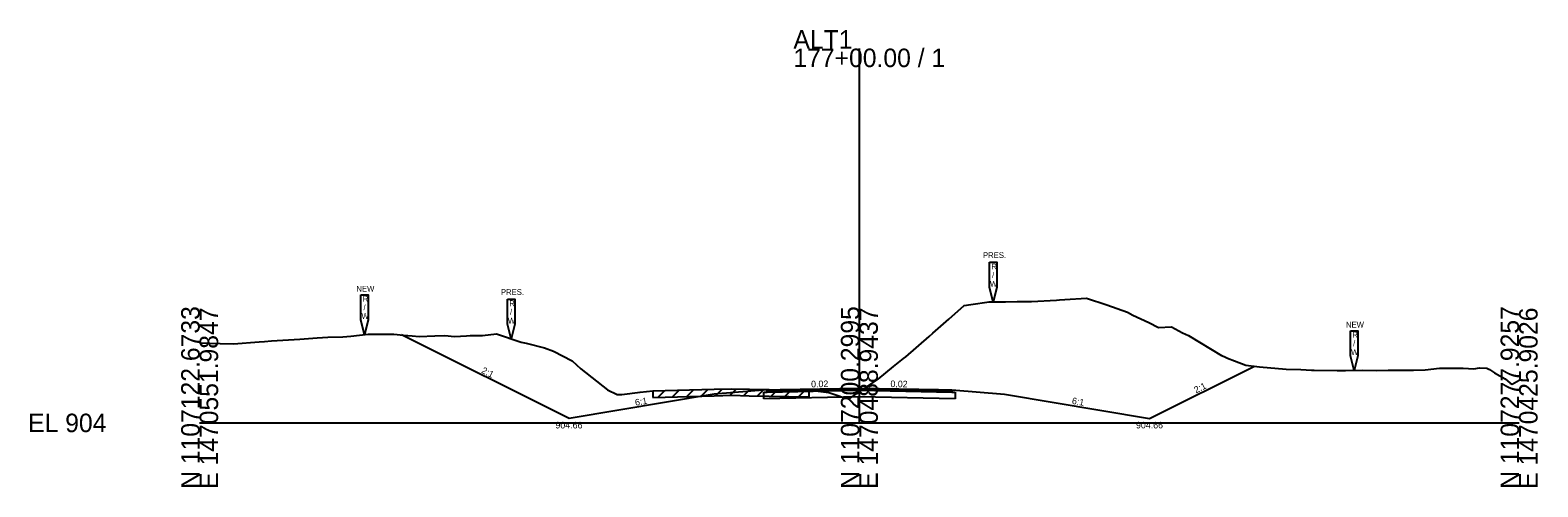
# Model space of a CAD drawing. Extents: x -26 to 2203, y -10 to 19568.
# Drawn here: x 974.3 to 1202.8, y 18990.3 to 19059.5 of the extents above; entities that cross this region are included whole.
import ezdxf

# ---------------------------------------------------------------- set-up
doc = ezdxf.new("R2010")
doc.units = 0
for name, color, linetype in [('RD_GPK_XS_Cell', 7, 'Continuous'), ('RD_XS_Base', 7, 'Continuous'), ('RD_XS_ExGround', 7, 'Continuous'), ('RD_XS_ExPaveRet', 7, 'Continuous'), ('RD_XS_ExRW', 7, 'Continuous'), ('RD_XS_Greenside', 7, 'Continuous'), ('RD_XS_NewRW', 7, 'Continuous'), ('RD_XS_Pave', 7, 'Continuous'), ('RD_XS_TieSlope', 7, 'Continuous'), ('RD_XS_TX_Slope', 7, 'Continuous')]:
    doc.layers.add(name, color=color, linetype=linetype)

msp = doc.modelspace()

# ---------------------------------------------------------------- linework, layer by layer
at = {"layer": 'RD_GPK_XS_Cell'}
for p, q in [((1100, 19000), (1100, 19056.73)), ((1000, 19000), (1100, 19000)), ((1100, 19000), (1200, 19000))]:
    msp.add_line(p, q, dxfattribs=at)
at = {"layer": 'RD_XS_Base'}
for points in [[(1085.5, 19004.67), (1086, 19004.68), (1100, 19004.96), (1114, 19004.68), (1114.5, 19004.67)], [(1085.5, 19003.67), (1085.5, 19004.67)], [(1114.5, 19003.67), (1100, 19003.96), (1085.5, 19003.67)], [(1114.5, 19004.67), (1114.5, 19003.67)]]:
    msp.add_lwpolyline(points, dxfattribs=at)
at = {"layer": 'RD_XS_ExGround'}
msp.add_lwpolyline([(1000, 19012.15), (1003.12, 19012.03), (1005.14, 19011.98), (1009.03, 19012.3), (1009.81, 19012.35), (1010.87, 19012.42), (1015.18, 19012.7), (1017.81, 19012.9), (1019.42, 19012.98), (1021.68, 19013.04), (1022.91, 19013.16), (1025.54, 19013.47), (1026.15, 19013.47), (1029.41, 19013.46), (1030.91, 19013.32), (1032.21, 19013.21), (1033.27, 19013.1), (1035.67, 19013.21), (1037.14, 19013.23), (1038.61, 19013.12), (1040.43, 19013.22), (1041, 19013.24), (1042.88, 19013.26), (1045.01, 19013.52), (1048.73, 19012.23), (1049.5, 19012.1), (1052.29, 19011.39), (1053.62, 19010.88), (1056.46, 19009.43), (1057.8, 19008.19), (1061.81, 19005.02), (1063.26, 19004.29), (1064.01, 19004.3), (1066.78, 19004.66), (1068.71, 19004.86), (1077.97, 19005.11), (1080.61, 19005.18), (1083.33, 19005.12), (1092.36, 19004.95), (1093.75, 19004.8), (1095.38, 19004.63), (1096.91, 19004.09), (1097.87, 19003.74), (1098.61, 19003.75), (1099.61, 19004.46), (1100, 19004.71), (1102.09, 19006.1), (1102.83, 19006.63), (1105.19, 19008.53), (1106.7, 19009.77), (1107.05, 19010.03), (1110.56, 19013.08), (1111.12, 19013.61), (1113.55, 19015.72), (1115.9, 19017.8), (1116.9, 19017.94), (1119.65, 19018.34), (1121.33, 19018.36), (1122.16, 19018.37), (1123.92, 19018.4), (1126.08, 19018.39), (1129.89, 19018.59), (1130.32, 19018.64), (1131.14, 19018.7), (1134.45, 19018.91), (1137.51, 19017.89), (1140.65, 19016.79), (1141.45, 19016.34), (1143.86, 19015.21), (1145.36, 19014.48), (1147.31, 19014.54), (1148.98, 19013.66), (1149.42, 19013.44), (1149.88, 19013.25), (1154.91, 19010.2), (1155.28, 19010.04), (1155.79, 19009.83), (1156.88, 19009.42), (1158.56, 19008.76), (1160.67, 19008.52), (1164.67, 19008.16), (1166.9, 19008.07), (1168.53, 19008.01), (1168.91, 19008.01), (1172.4, 19007.94), (1173.67, 19007.94), (1176.26, 19007.97), (1178.43, 19007.96), (1180.13, 19007.98), (1183.19, 19007.98), (1183.99, 19007.99), (1185.77, 19008.02), (1187.95, 19008.28), (1191.53, 19008.31), (1193.14, 19008.2), (1194.01, 19008.37), (1195.12, 19008.29), (1195.5, 19008.09), (1196.29, 19007.58), (1197.87, 19006.66), (1198.62, 19006.03), (1198.97, 19005.88), (1200, 19006.49)], dxfattribs=at)
at = {"layer": 'RD_XS_ExPaveRet'}
for p, q in [((1068.71, 19004.86), (1068.71, 19003.86)), ((1069.49, 19003.88), (1070.51, 19004.91)), ((1071.67, 19003.94), (1072.69, 19004.97)), ((1073.84, 19004), (1074.87, 19005.02)), ((1076.02, 19004.05), (1077.05, 19005.08)), ((1078.2, 19004.11), (1079.23, 19005.14)), ((1080.38, 19004.17), (1081.37, 19005.16)), ((1082.47, 19004.14), (1083.45, 19005.12)), ((1084.55, 19004.1), (1085.53, 19005.08)), ((1086.63, 19004.06), (1087.62, 19005.04)), ((1088.72, 19004.02), (1089.7, 19005)), ((1090.8, 19003.98), (1091.78, 19004.96)), ((1092.36, 19004.95), (1092.36, 19003.95))]:
    msp.add_line(p, q, dxfattribs=at)
msp.add_lwpolyline([(1068.71, 19003.86), (1078, 19004.11), (1080.62, 19004.18), (1083.31, 19004.12), (1092.36, 19003.95)], dxfattribs=at)
at = {"layer": 'RD_XS_ExRW'}
for points in [[(1119.73, 19024.36), (1120.82, 19024.36), (1120.82, 19020.53), (1120.27, 19018.34), (1119.73, 19020.53)], [(1046.66, 19018.77), (1047.75, 19018.77), (1047.75, 19014.94), (1047.2, 19012.75), (1046.66, 19014.94)]]:
    msp.add_lwpolyline(points, close=True, dxfattribs=at)
at = {"layer": 'RD_XS_Greenside'}
for points in [[(1086, 19005), (1078, 19004.33)], [(1114, 19005), (1122, 19004.33)], [(1078, 19004.33), (1056, 19000.66)], [(1122, 19004.33), (1144, 19000.66)]]:
    msp.add_lwpolyline(points, dxfattribs=at)
at = {"layer": 'RD_XS_NewRW'}
for points in [[(1024.45, 19019.42), (1025.55, 19019.42), (1025.55, 19015.59), (1025, 19013.41), (1024.45, 19015.59)], [(1174.45, 19013.97), (1175.55, 19013.97), (1175.55, 19010.14), (1175, 19007.95), (1174.45, 19010.14)]]:
    msp.add_lwpolyline(points, close=True, dxfattribs=at)
at = {"layer": 'RD_XS_Pave'}
for points in [[(1086, 19005), (1088, 19005.04), (1100, 19005.28), (1112, 19005.04), (1114, 19005)], [(1086, 19004.84), (1100, 19005.12), (1114, 19004.84)], [(1114, 19004.84), (1100, 19005.12), (1086, 19004.84)], [(1086, 19004.84), (1086, 19005)], [(1114, 19004.68), (1100, 19004.96), (1086, 19004.68)], [(1086, 19004.68), (1086, 19004.84)], [(1114, 19005), (1114, 19004.84)], [(1114, 19004.84), (1114, 19004.68)]]:
    msp.add_lwpolyline(points, dxfattribs=at)
at = {"layer": 'RD_XS_TieSlope'}
for points in [[(1056, 19000.66), (1030.62, 19013.35)], [(1144, 19000.66), (1159.9, 19008.61)]]:
    msp.add_lwpolyline(points, dxfattribs=at)

# ---------------------------------------------------------------- texts
at = {"layer": 'RD_GPK_XS_Cell'}
for s, p in [('ALT1', (1090, 19056.73)), ('177+00.00 / 1', (1090, 19053.93)), ('EL 904', (974, 18998.6))]:
    msp.add_text(s, height=2.8, dxfattribs=at).set_placement(p)
for s, p in [('N 1107122.6733', (1000, 18990)), ('E 1470551.9847', (1002.8, 18990)), ('N 1107200.2995', (1100, 18990)), ('E 1470488.9437', (1102.8, 18990)), ('N 1107277.9257', (1200, 18990)), ('E 1470425.9026', (1202.8, 18990))]:
    msp.add_text(s, height=2.8, rotation=90, dxfattribs=at).set_placement(p)
at = {"layer": 'RD_XS_ExRW'}
for s, p in [('PRES.', (1118.73, 19024.99)), ('R', (1119.99, 19023.27)), ('W', (1119.8, 19020.64)), ('/', (1120.11, 19021.96)), ('PRES.', (1045.66, 19019.4)), ('R', (1046.92, 19017.68)), ('/', (1047.04, 19016.37)), ('W', (1046.73, 19015.05))]:
    msp.add_text(s, height=0.875, dxfattribs=at).set_placement(p)
at = {"layer": 'RD_XS_NewRW'}
for s, p in [('NEW', (1023.75, 19019.9)), ('R', (1024.71, 19018.38)), ('W', (1024.53, 19015.76)), ('/', (1024.83, 19017.07)), ('NEW', (1173.75, 19014.45)), ('R', (1174.71, 19012.93)), ('/', (1174.83, 19011.62)), ('W', (1174.53, 19010.3))]:
    msp.add_text(s, height=0.875, dxfattribs=at).set_placement(p)
at = {"layer": 'RD_XS_TX_Slope'}
for s, rotation, p in [('2:1', 333.4349, (1042.62, 19007.63)), ('0.02', 1.1458, (1092.69, 19005.38)), ('0.02', 358.8542, (1104.7, 19005.43)), ('2:1', 26.5651, (1151.03, 19004.46)), ('6:1', 9.4642, (1066.07, 19002.59)), ('6:1', 350.5358, (1132.16, 19002.89))]:
    msp.add_text(s, height=1, rotation=rotation, dxfattribs=at).set_placement(p)
for p in [(1053.93, 18999.16), (1141.93, 18999.16)]:
    msp.add_text('904.66', height=1, dxfattribs=at).set_placement(p)

doc.saveas('drawing.dxf')
